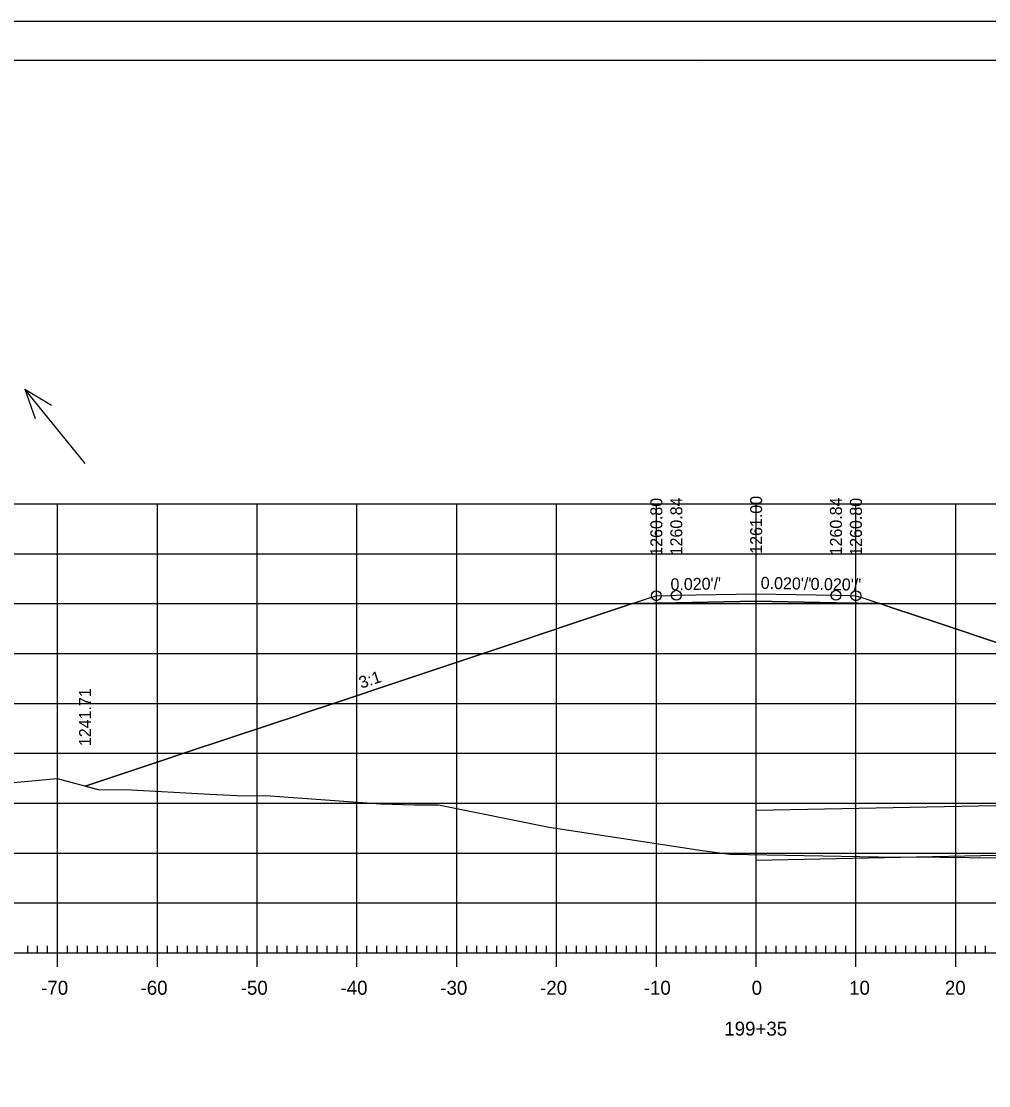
# Model space of a CAD drawing. Extents: x 1406028 to 1412453, y 321733 to 325986.
# Drawn here: x 1408981.2 to 1409078.1, y 321949.6 to 322056.2 of the extents above; entities that cross this region are included whole.
import ezdxf

# ---------------------------------------------------------------- set-up
doc = ezdxf.new("R2010")
doc.units = 0
for name, color, linetype in [('R_Alt Surface', 7, 'Continuous'), ('R_Axis', 7, 'Continuous'), ('R_Axis Annot', 7, 'Continuous'), ('R_Border', 7, 'Continuous'), ('R_Exist Surface', 7, 'Continuous'), ('R_Fin Surface', 7, 'Continuous'), ('R_Fin Surface Annot', 7, 'Continuous'), ('R_Grid', 7, 'Continuous'), ('R_No Plot', 7, 'Continuous'), ('R_Water', 7, 'Continuous'), ('R_Water Annot', 7, 'Continuous')]:
    doc.layers.add(name, color=color, linetype=linetype)

msp = doc.modelspace()

# ---------------------------------------------------------------- linework, layer by layer
at = {"layer": 'R_Alt Surface'}
msp.add_lwpolyline([(1409042.42, 321997.87), (1409046.81, 321997.96), (1409054.81, 321998.12), (1409062.81, 321997.96), (1409067.2, 321997.87)], dxfattribs=at)
at = {"layer": 'R_Axis'}
for p, q in [((1408984.81, 321961.48), (1408984.81, 321964.28)), ((1408994.81, 321961.48), (1408994.81, 321964.28)), ((1409004.81, 321961.48), (1409004.81, 321964.28)), ((1409014.81, 321961.48), (1409014.81, 321964.28)), ((1409024.81, 321961.48), (1409024.81, 321964.28)), ((1409034.81, 321961.48), (1409034.81, 321964.28)), ((1409044.81, 321961.48), (1409044.81, 321964.28)), ((1409054.81, 321961.48), (1409054.81, 321964.28)), ((1409064.81, 321961.48), (1409064.81, 321964.28)), ((1409074.81, 321961.48), (1409074.81, 321964.28)), ((1408914.81, 321962.88), (1409194.81, 321962.88)), ((1408981.81, 321962.88), (1408981.81, 321963.58)), ((1408982.81, 321962.88), (1408982.81, 321963.58)), ((1408983.81, 321962.88), (1408983.81, 321963.58)), ((1408985.81, 321962.88), (1408985.81, 321963.58)), ((1408986.81, 321962.88), (1408986.81, 321963.58)), ((1408987.81, 321962.88), (1408987.81, 321963.58)), ((1408988.81, 321962.88), (1408988.81, 321963.58)), ((1408989.81, 321962.88), (1408989.81, 321963.58)), ((1408990.81, 321962.88), (1408990.81, 321963.58)), ((1408991.81, 321962.88), (1408991.81, 321963.58)), ((1408992.81, 321962.88), (1408992.81, 321963.58)), ((1408993.81, 321962.88), (1408993.81, 321963.58)), ((1408995.81, 321962.88), (1408995.81, 321963.58)), ((1408996.81, 321962.88), (1408996.81, 321963.58)), ((1408997.81, 321962.88), (1408997.81, 321963.58)), ((1408998.81, 321962.88), (1408998.81, 321963.58)), ((1408999.81, 321962.88), (1408999.81, 321963.58)), ((1409000.81, 321962.88), (1409000.81, 321963.58)), ((1409001.81, 321962.88), (1409001.81, 321963.58)), ((1409002.81, 321962.88), (1409002.81, 321963.58)), ((1409003.81, 321962.88), (1409003.81, 321963.58)), ((1409005.81, 321962.88), (1409005.81, 321963.58)), ((1409006.81, 321962.88), (1409006.81, 321963.58)), ((1409007.81, 321962.88), (1409007.81, 321963.58)), ((1409008.81, 321962.88), (1409008.81, 321963.58)), ((1409009.81, 321962.88), (1409009.81, 321963.58)), ((1409010.81, 321962.88), (1409010.81, 321963.58)), ((1409011.81, 321962.88), (1409011.81, 321963.58)), ((1409012.81, 321962.88), (1409012.81, 321963.58)), ((1409013.81, 321962.88), (1409013.81, 321963.58)), ((1409015.81, 321962.88), (1409015.81, 321963.58)), ((1409016.81, 321962.88), (1409016.81, 321963.58)), ((1409017.81, 321962.88), (1409017.81, 321963.58)), ((1409018.81, 321962.88), (1409018.81, 321963.58)), ((1409019.81, 321962.88), (1409019.81, 321963.58)), ((1409020.81, 321962.88), (1409020.81, 321963.58)), ((1409021.81, 321962.88), (1409021.81, 321963.58)), ((1409022.81, 321962.88), (1409022.81, 321963.58)), ((1409023.81, 321962.88), (1409023.81, 321963.58)), ((1409025.81, 321962.88), (1409025.81, 321963.58)), ((1409026.81, 321962.88), (1409026.81, 321963.58)), ((1409027.81, 321962.88), (1409027.81, 321963.58)), ((1409028.81, 321962.88), (1409028.81, 321963.58)), ((1409029.81, 321962.88), (1409029.81, 321963.58)), ((1409030.81, 321962.88), (1409030.81, 321963.58)), ((1409031.81, 321962.88), (1409031.81, 321963.58)), ((1409032.81, 321962.88), (1409032.81, 321963.58)), ((1409033.81, 321962.88), (1409033.81, 321963.58)), ((1409035.81, 321962.88), (1409035.81, 321963.58)), ((1409036.81, 321962.88), (1409036.81, 321963.58)), ((1409037.81, 321962.88), (1409037.81, 321963.58)), ((1409038.81, 321962.88), (1409038.81, 321963.58)), ((1409039.81, 321962.88), (1409039.81, 321963.58)), ((1409040.81, 321962.88), (1409040.81, 321963.58)), ((1409041.81, 321962.88), (1409041.81, 321963.58)), ((1409042.81, 321962.88), (1409042.81, 321963.58)), ((1409043.81, 321962.88), (1409043.81, 321963.58)), ((1409045.81, 321962.88), (1409045.81, 321963.58)), ((1409046.81, 321962.88), (1409046.81, 321963.58)), ((1409047.81, 321962.88), (1409047.81, 321963.58)), ((1409048.81, 321962.88), (1409048.81, 321963.58)), ((1409049.81, 321962.88), (1409049.81, 321963.58)), ((1409050.81, 321962.88), (1409050.81, 321963.58)), ((1409051.81, 321962.88), (1409051.81, 321963.58)), ((1409052.81, 321962.88), (1409052.81, 321963.58)), ((1409053.81, 321962.88), (1409053.81, 321963.58)), ((1409055.81, 321962.88), (1409055.81, 321963.58)), ((1409056.81, 321962.88), (1409056.81, 321963.58)), ((1409057.81, 321962.88), (1409057.81, 321963.58)), ((1409058.81, 321962.88), (1409058.81, 321963.58)), ((1409059.81, 321962.88), (1409059.81, 321963.58)), ((1409060.81, 321962.88), (1409060.81, 321963.58)), ((1409061.81, 321962.88), (1409061.81, 321963.58)), ((1409062.81, 321962.88), (1409062.81, 321963.58)), ((1409063.81, 321962.88), (1409063.81, 321963.58)), ((1409065.81, 321962.88), (1409065.81, 321963.58)), ((1409066.81, 321962.88), (1409066.81, 321963.58)), ((1409067.81, 321962.88), (1409067.81, 321963.58)), ((1409068.81, 321962.88), (1409068.81, 321963.58)), ((1409069.81, 321962.88), (1409069.81, 321963.58)), ((1409070.81, 321962.88), (1409070.81, 321963.58)), ((1409071.81, 321962.88), (1409071.81, 321963.58)), ((1409072.81, 321962.88), (1409072.81, 321963.58)), ((1409073.81, 321962.88), (1409073.81, 321963.58)), ((1409075.81, 321962.88), (1409075.81, 321963.58)), ((1409076.81, 321962.88), (1409076.81, 321963.58)), ((1409077.81, 321962.88), (1409077.81, 321963.58))]:
    msp.add_line(p, q, dxfattribs=at)
at = {"layer": 'R_Border'}
for p, q in [((1408896.81, 322052.34), (1409212.99, 322052.34)), ((1409049.33, 322052.08), (1409049.33, 322052.08)), ((1409049.33, 322052.08), (1409049.33, 322052.08))]:
    msp.add_line(p, q, dxfattribs=at)
at = {"layer": 'R_Exist Surface'}
msp.add_lwpolyline([(1408972, 321979.18), (1408984.77, 321980.34), (1408989, 321979.2), (1408991.6, 321979.26), (1409000.06, 321978.78), (1409003.44, 321978.61), (1409005.61, 321978.66), (1409005.63, 321978.66), (1409005.65, 321978.66), (1409017.2, 321977.82), (1409020.56, 321977.72), (1409022.98, 321977.7), (1409034.08, 321975.46), (1409049.39, 321973.14), (1409050.68, 321972.96), (1409052.19, 321972.76), (1409067.06, 321972.51), (1409073.22, 321972.48), (1409082.09, 321972.37)], dxfattribs=at)
at = {"layer": 'R_Fin Surface'}
msp.add_lwpolyline([(1408987.56, 321979.59), (1408995.09, 321982.09), (1408997.66, 321982.94), (1409006.14, 321985.76), (1409008.99, 321986.71), (1409009.03, 321986.72), (1409013.16, 321988.1), (1409018.74, 321989.96), (1409031.75, 321994.31), (1409033.05, 321994.74), (1409036.81, 321996.01), (1409041.03, 321997.41), (1409042.42, 321997.87), (1409044.23, 321998.48), (1409044.81, 321998.67), (1409046.32, 321998.7), (1409046.81, 321998.71), (1409052.81, 321998.83), (1409054.81, 321998.87), (1409060.81, 321998.75), (1409062.81, 321998.71), (1409064.32, 321998.68), (1409064.81, 321998.67), (1409065.39, 321998.48), (1409067.2, 321997.87), (1409068.54, 321997.43), (1409072.81, 321996.01), (1409093.77, 321989)], dxfattribs=at)
at = {"layer": 'R_Grid'}
for p, q in [((1408914.81, 322007.88), (1409194.81, 322007.88)), ((1408984.81, 321962.88), (1408984.81, 322007.88)), ((1408994.81, 321962.88), (1408994.81, 322007.88)), ((1409004.81, 321962.88), (1409004.81, 322007.88)), ((1409014.81, 321962.88), (1409014.81, 322007.88)), ((1409024.81, 321962.88), (1409024.81, 322007.88)), ((1409034.81, 321962.88), (1409034.81, 322007.88)), ((1409044.81, 321962.88), (1409044.81, 322007.88)), ((1409054.81, 321962.88), (1409054.81, 322007.88)), ((1409064.81, 321962.88), (1409064.81, 322007.88)), ((1409074.81, 321962.88), (1409074.81, 322007.88)), ((1408914.81, 322002.88), (1409194.81, 322002.88)), ((1408914.81, 321997.88), (1409194.81, 321997.88)), ((1408914.81, 321992.88), (1409194.81, 321992.88)), ((1408914.81, 321987.88), (1409194.81, 321987.88)), ((1408914.81, 321982.88), (1409194.81, 321982.88)), ((1408914.81, 321977.88), (1409194.81, 321977.88)), ((1408914.81, 321972.88), (1409194.81, 321972.88)), ((1408914.81, 321967.88), (1409194.81, 321967.88)), ((1408914.81, 321962.88), (1409194.81, 321962.88))]:
    msp.add_line(p, q, dxfattribs=at)
at = {"layer": 'R_No Plot'}
msp.add_line((1408884.41, 322056.23), (1409217.75, 322056.23), dxfattribs=at)
for points in [[(1408884.41, 322056.23), (1409217.75, 322056.23), (1409217.75, 321842.89), (1408884.41, 321842.89)], [(1409130.73, 322052.34), (1409150.35, 322052.34), (1409150.35, 322042.46), (1409166.47, 322042.46), (1409189.67, 322042.46), (1409189.67, 322018.12), (1409212.99, 322018.12), (1409212.99, 321846.88), (1408896.81, 321846.88), (1408896.81, 322052.34)]]:
    msp.add_lwpolyline(points, close=True, dxfattribs=at)
msp.add_lwpolyline([(1409093.77, 321989), (1409072.81, 321996.01), (1409068.54, 321997.43), (1409067.2, 321997.87), (1409062.81, 321997.96), (1409054.81, 321998.12), (1409046.81, 321997.96), (1409042.42, 321997.87), (1409041.03, 321997.41), (1409036.81, 321996.01), (1409033.05, 321994.74), (1409031.75, 321994.31), (1409018.74, 321989.96), (1409013.16, 321988.1), (1409009.03, 321986.72), (1409008.99, 321986.71), (1409006.14, 321985.76), (1408997.66, 321982.94), (1408995.09, 321982.09), (1408987.56, 321979.59), (1408989, 321979.2), (1408991.6, 321979.26), (1409000.06, 321978.78), (1409003.44, 321978.61), (1409005.61, 321978.66), (1409005.63, 321978.66), (1409005.65, 321978.66), (1409017.2, 321977.82), (1409020.56, 321977.72), (1409022.98, 321977.7), (1409034.08, 321975.46), (1409049.39, 321973.14), (1409050.68, 321972.96), (1409052.19, 321972.76), (1409067.06, 321972.51), (1409073.22, 321972.48), (1409082.09, 321972.37)], dxfattribs=at)
for centre in [(1409044.81, 321998.67), (1409046.81, 321998.71), (1409062.81, 321998.71), (1409064.81, 321998.67)]:
    msp.add_circle(centre, 0.5, dxfattribs=at)
at = {"layer": 'R_Water'}
for p, q in [((1409054.81, 321977.16), (1409125.03, 321978.59)), ((1409054.81, 321972.16), (1409139.19, 321973.88))]:
    msp.add_line(p, q, dxfattribs=at)
at = {"layer": 'R_Water Annot'}
for p, q in [((1408987.57, 322011.93), (1408981.52, 322019.35)), ((1408981.52, 322019.35), (1408984.2, 322017.76)), ((1408981.52, 322019.35), (1408982.55, 322016.41))]:
    msp.add_line(p, q, dxfattribs=at)

# ---------------------------------------------------------------- texts
at = {"layer": 'R_Axis Annot'}
for s, p in [('-70', (1408983.16, 321958.68)), ('-60', (1408993.12, 321958.68)), ('-50', (1409003.16, 321958.68)), ('-40', (1409013.16, 321958.68)), ('-30', (1409023.16, 321958.68)), ('-20', (1409033.16, 321958.68)), ('-10', (1409043.55, 321958.68)), ('0', (1409054.36, 321958.68)), ('10', (1409064.13, 321958.68)), ('20', (1409073.73, 321958.68)), ('199+35', (1409051.62, 321954.58))]:
    msp.add_text(s, height=1.4, dxfattribs=at).set_placement(p)
at = {"layer": 'R_Fin Surface Annot'}
for s, rotation, p in [('1261.00', 90, (1409055.41, 322002.87)), ('1260.80', 90, (1409045.41, 322002.67)), ('1260.84', 90, (1409047.41, 322002.71)), ('1260.84', 90, (1409063.41, 322002.71)), ('1260.80', 90, (1409065.41, 322002.67)), ("0.020'/'", 1.1458, (1409046.24, 321999.2)), ("0.020'/'", 358.8542, (1409055.26, 321999.36)), ("0.020'/'", 358.8542, (1409060.26, 321999.26)), ('3:1', 18.4352, (1409015.24, 321989.34)), ('1241.71', 90, (1408988.16, 321983.59))]:
    msp.add_text(s, height=1.2, rotation=rotation, dxfattribs=at).set_placement(p)

doc.saveas('drawing.dxf')
